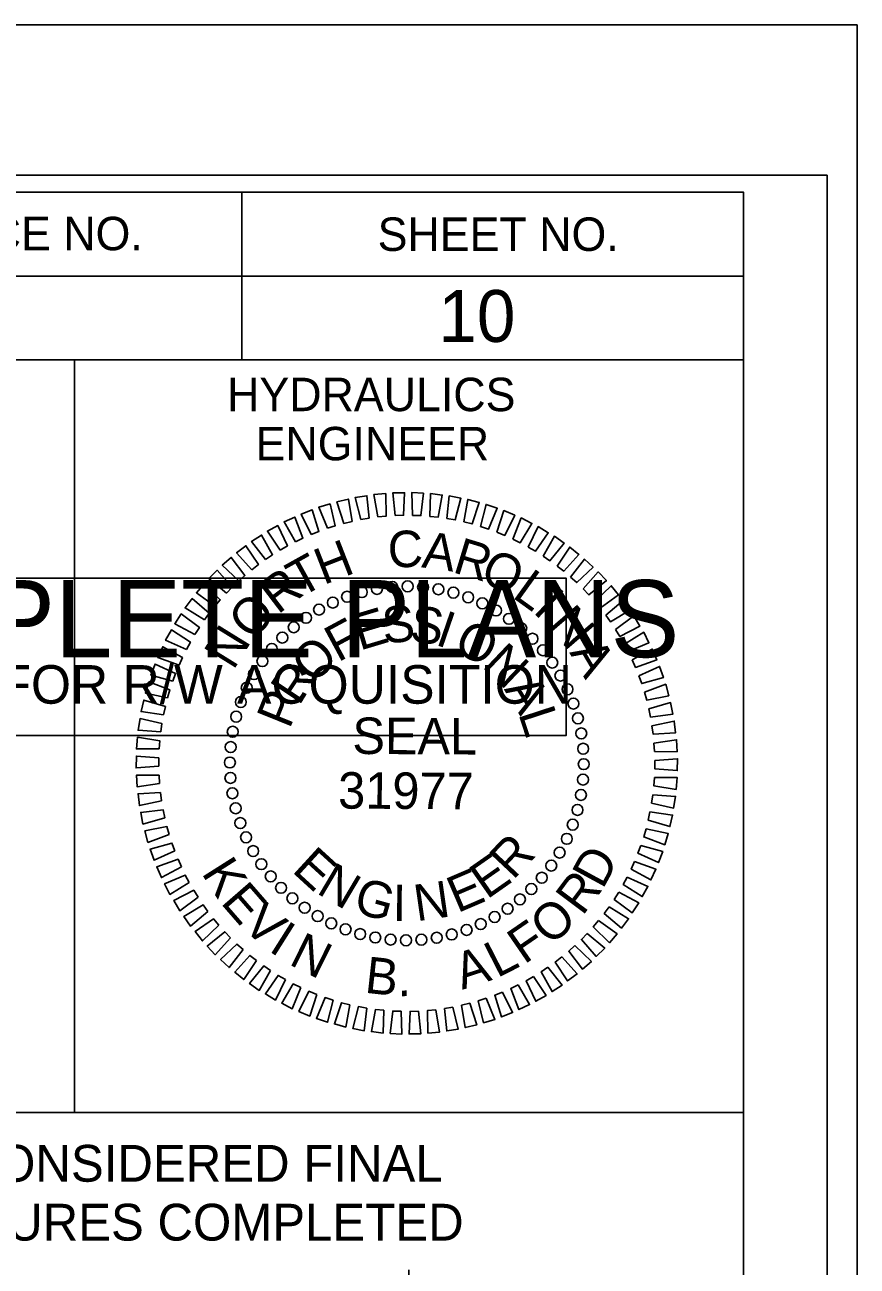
# Model space of a CAD drawing. Extents: x 557032 to 558716, y 513430 to 514605.
# Drawn here: x 558592 to 558716.5, y 514344.9 to 514530.4 of the extents above; entities that cross this region are included whole.
import ezdxf

# ---------------------------------------------------------------- set-up
doc = ezdxf.new("R2010")
doc.units = 0
for name, color, linetype in [('Default', 7, 'Continuous'), ('Sheet Cutting Line CELL', 7, 'Continuous'), ('Sheet Data Field CELL', 7, 'Continuous'), ('Sheet Plot Border Inside CELL', 7, 'Continuous'), ('Sheet Plot Border Outside CELL', 7, 'Continuous'), ('Sheet Profile CELL', 7, 'Continuous'), ('Sheet Profile Grid Major CELL', 7, 'Continuous'), ('Sheet Sticker Exception Certification CELL', 7, 'Continuous'), ('Sheet Sticker Incomplete CELL', 7, 'Continuous')]:
    doc.layers.add(name, color=color, linetype=linetype)

msp = doc.modelspace()

# ---------------------------------------------------------------- linework, layer by layer
at = {"layer": 'Default'}
for points in [[(558639.73, 514455.89), (558638.68, 514459.12), (558640.4, 514459.51), (558640.94, 514456.19)], [(558642.26, 514456.46), (558641.43, 514459.76), (558643.17, 514460.03), (558643.48, 514456.68)], [(558644.81, 514456.85), (558644.22, 514460.2), (558645.98, 514460.34), (558646.05, 514456.98)], [(558647.39, 514457.06), (558647.03, 514460.44), (558648.8, 514460.47), (558648.64, 514457.11)], [(558649.98, 514457.09), (558649.86, 514460.49), (558651.62, 514460.39), (558651.23, 514457.05)], [(558652.56, 514456.94), (558652.68, 514460.34), (558654.43, 514460.12), (558653.8, 514456.81)], [(558655.13, 514456.61), (558655.48, 514460), (558657.21, 514459.65), (558656.36, 514456.4)], [(558657.67, 514456.1), (558658.25, 514459.46), (558659.95, 514458.99), (558658.88, 514455.8)], [(558634.83, 514454.23), (558633.34, 514457.29), (558634.99, 514457.91), (558635.99, 514454.7)], [(558637.25, 514455.15), (558635.97, 514458.3), (558637.66, 514458.81), (558638.44, 514455.53)], [(558660.16, 514455.42), (558660.98, 514458.72), (558662.65, 514458.14), (558661.35, 514455.04)], [(558662.61, 514454.56), (558663.65, 514457.8), (558665.27, 514457.11), (558663.76, 514454.1)], [(558630.21, 514451.91), (558628.3, 514454.73), (558629.85, 514455.57), (558631.29, 514452.53)], [(558632.48, 514453.15), (558630.78, 514456.1), (558632.38, 514456.83), (558633.6, 514453.7)], [(558664.98, 514453.54), (558666.25, 514456.7), (558667.82, 514455.89), (558666.1, 514453)], [(558667.28, 514452.35), (558668.77, 514455.41), (558670.28, 514454.5), (558668.36, 514451.73)], [(558628.03, 514450.51), (558625.93, 514453.19), (558627.42, 514454.14), (558629.07, 514451.21)], [(558669.49, 514451.01), (558671.19, 514453.96), (558672.63, 514452.94), (558670.53, 514450.31)], [(558625.96, 514448.97), (558623.68, 514451.49), (558625.09, 514452.55), (558626.94, 514449.73)], [(558671.6, 514449.51), (558673.5, 514452.34), (558674.87, 514451.22), (558672.59, 514448.75)], [(558624, 514447.28), (558621.55, 514449.64), (558622.88, 514450.79), (558624.92, 514448.11)], [(558673.61, 514447.87), (558675.7, 514450.56), (558676.98, 514449.35), (558674.53, 514447.04)], [(558622.16, 514445.46), (558619.55, 514447.64), (558620.8, 514448.88), (558623.02, 514446.36)], [(558675.49, 514446.1), (558677.76, 514448.63), (558678.96, 514447.34), (558676.36, 514445.2)], [(558620.45, 514443.52), (558617.69, 514445.51), (558618.86, 514446.84), (558621.25, 514444.47)], [(558677.24, 514444.2), (558679.69, 514446.56), (558680.79, 514445.19), (558678.04, 514443.24)], [(558618.88, 514441.46), (558615.99, 514443.26), (558617.06, 514444.66), (558619.61, 514442.47)], [(558678.86, 514442.18), (558681.46, 514444.37), (558682.47, 514442.92), (558679.59, 514441.17)], [(558617.46, 514439.3), (558614.45, 514440.89), (558615.42, 514442.36), (558618.12, 514440.35)], [(558680.33, 514440.05), (558683.08, 514442.05), (558683.98, 514440.54), (558680.99, 514438.99)], [(558616.19, 514437.04), (558613.08, 514438.42), (558613.94, 514439.96), (558616.78, 514438.14)], [(558681.65, 514437.82), (558684.54, 514439.63), (558685.33, 514438.06), (558682.24, 514436.72)], [(558615.09, 514434.7), (558611.89, 514435.86), (558612.64, 514437.45), (558615.59, 514435.84)], [(558682.82, 514435.51), (558685.82, 514437.11), (558686.5, 514435.49), (558683.32, 514434.37)], [(558614.15, 514432.29), (558610.87, 514433.22), (558611.51, 514434.87), (558614.57, 514433.46)], [(558683.81, 514433.12), (558686.92, 514434.51), (558687.49, 514432.84), (558684.24, 514431.95)], [(558613.38, 514429.82), (558610.05, 514430.52), (558610.57, 514432.2), (558613.72, 514431.02)], [(558684.64, 514430.67), (558687.84, 514431.84), (558688.29, 514430.14), (558684.99, 514429.48)], [(558612.78, 514427.3), (558609.41, 514427.77), (558609.81, 514429.49), (558613.04, 514428.52)], [(558685.3, 514428.17), (558688.57, 514429.11), (558688.9, 514427.38), (558685.56, 514426.95)], [(558612.36, 514424.75), (558608.97, 514424.98), (558609.25, 514426.72), (558612.53, 514425.98)], [(558685.78, 514425.63), (558689.11, 514426.34), (558689.31, 514424.59), (558685.95, 514424.39)], [(558612.12, 514422.17), (558608.72, 514422.17), (558608.88, 514423.92), (558612.21, 514423.41)], [(558686.08, 514423.06), (558689.45, 514423.54), (558689.53, 514421.77), (558686.17, 514421.81)], [(558612.06, 514419.58), (558608.67, 514419.34), (558608.71, 514421.1), (558612.06, 514420.83)], [(558686.2, 514420.47), (558689.6, 514420.71), (558689.56, 514418.95), (558686.2, 514419.23)], [(558612.18, 514417), (558608.81, 514416.52), (558608.73, 514418.28), (558612.09, 514418.24)], [(558686.14, 514417.89), (558689.55, 514417.89), (558689.38, 514416.14), (558686.06, 514416.64)], [(558612.48, 514414.43), (558609.16, 514413.72), (558608.95, 514415.47), (558612.31, 514415.66)], [(558685.9, 514415.31), (558689.3, 514415.08), (558689.01, 514413.34), (558685.73, 514414.08)], [(558612.96, 514411.89), (558609.69, 514410.94), (558609.37, 514412.68), (558612.7, 514413.1)], [(558685.48, 514412.76), (558688.85, 514412.29), (558688.45, 514410.57), (558685.23, 514411.54)], [(558613.62, 514409.38), (558610.42, 514408.21), (558609.98, 514409.92), (558613.28, 514410.58)], [(558684.89, 514410.24), (558688.22, 514409.53), (558687.69, 514407.85), (558684.55, 514409.04)], [(558614.45, 514406.93), (558611.34, 514405.54), (558610.78, 514407.21), (558614.02, 514408.1)], [(558684.12, 514407.77), (558687.39, 514406.83), (558686.75, 514405.19), (558683.69, 514406.6)], [(558615.45, 514404.54), (558612.44, 514402.94), (558611.76, 514404.57), (558614.94, 514405.68)], [(558683.18, 514405.36), (558686.38, 514404.2), (558685.62, 514402.6), (558682.67, 514404.22)], [(558616.61, 514402.23), (558613.73, 514400.43), (558612.93, 514402), (558616.02, 514403.33)], [(558682.07, 514403.02), (558685.18, 514401.64), (558684.32, 514400.1), (558681.49, 514401.92)], [(558617.93, 514400.01), (558615.18, 514398), (558614.28, 514399.52), (558617.27, 514401.06)], [(558680.8, 514400.76), (558683.81, 514399.17), (558682.84, 514397.69), (558680.15, 514399.7)], [(558619.4, 514397.88), (558616.8, 514395.69), (558615.8, 514397.14), (558618.67, 514398.89)], [(558679.38, 514398.6), (558682.27, 514396.8), (558681.2, 514395.4), (558678.65, 514397.59)], [(558621.02, 514395.86), (558618.58, 514393.49), (558617.47, 514394.87), (558620.22, 514396.81)], [(558677.81, 514396.54), (558680.57, 514394.54), (558679.41, 514393.22), (558677.01, 514395.59)], [(558622.77, 514393.96), (558620.5, 514391.43), (558619.31, 514392.72), (558621.91, 514394.85)], [(558676.11, 514394.6), (558678.72, 514392.41), (558677.46, 514391.17), (558675.24, 514393.7)], [(558624.66, 514392.18), (558622.57, 514389.5), (558621.28, 514390.71), (558623.73, 514393.02)], [(558674.27, 514392.78), (558676.72, 514390.42), (558675.38, 514389.27), (558673.34, 514391.94)], [(558626.66, 514390.54), (558624.76, 514387.72), (558623.4, 514388.84), (558625.68, 514391.31)], [(558672.3, 514391.09), (558674.58, 514388.56), (558673.17, 514387.51), (558671.32, 514390.32)], [(558628.77, 514389.05), (558627.07, 514386.1), (558625.63, 514387.12), (558627.74, 514389.74)], [(558670.23, 514389.55), (558672.33, 514386.87), (558670.84, 514385.91), (558669.2, 514388.85)], [(558630.98, 514387.7), (558629.49, 514384.64), (558627.99, 514385.56), (558629.9, 514388.32)], [(558633.28, 514386.52), (558632.01, 514383.36), (558630.44, 514384.17), (558632.16, 514387.06)], [(558665.78, 514386.91), (558667.49, 514383.96), (558665.89, 514383.22), (558664.66, 514386.36)], [(558668.05, 514388.15), (558669.96, 514385.33), (558668.41, 514384.48), (558666.97, 514387.52)], [(558635.66, 514385.49), (558634.61, 514382.25), (558632.99, 514382.95), (558634.5, 514385.96)], [(558638.1, 514384.64), (558637.28, 514381.33), (558635.62, 514381.91), (558636.91, 514385.02)], [(558661.01, 514384.91), (558662.29, 514381.76), (558660.6, 514381.25), (558659.82, 514384.52)], [(558663.43, 514385.82), (558664.93, 514382.77), (558663.28, 514382.14), (558662.28, 514385.36)], [(558640.59, 514383.95), (558640.01, 514380.6), (558638.31, 514381.07), (558639.39, 514384.25)], [(558643.13, 514383.45), (558642.78, 514380.06), (558641.05, 514380.4), (558641.9, 514383.66)], [(558645.7, 514383.12), (558645.58, 514379.71), (558643.84, 514379.94), (558644.46, 514383.24)], [(558648.28, 514382.97), (558648.41, 514379.56), (558646.65, 514379.67), (558647.04, 514383.01)], [(558650.87, 514383), (558651.23, 514379.61), (558649.47, 514379.59), (558649.62, 514382.95)], [(558653.45, 514383.21), (558654.04, 514379.86), (558652.29, 514379.71), (558652.21, 514383.08)], [(558656.01, 514383.6), (558656.83, 514380.3), (558655.09, 514380.03), (558654.78, 514383.38)], [(558658.53, 514384.17), (558659.59, 514380.93), (558657.87, 514380.54), (558657.32, 514383.86)]]:
    msp.add_lwpolyline(points, close=True, dxfattribs=at)
for centre in [(558642.41, 514445.61), (558644.66, 514446.1), (558646.95, 514446.39), (558649.26, 514446.48), (558651.56, 514446.36), (558653.85, 514446.05), (558656.1, 514445.54), (558638.07, 514444.05), (558640.2, 514444.92), (558658.3, 514444.84), (558660.42, 514443.94), (558634.07, 514441.77), (558636.02, 514443), (558662.46, 514442.87), (558664.4, 514441.62), (558632.23, 514440.37), (558666.23, 514440.21), (558630.52, 514438.82), (558667.92, 514438.64), (558628.95, 514437.13), (558669.47, 514436.93), (558627.54, 514435.3), (558670.87, 514435.09), (558626.29, 514433.36), (558672.1, 514433.14), (558625.21, 514431.32), (558673.15, 514431.09), (558624.32, 514429.19), (558674.03, 514428.96), (558623.62, 514427), (558674.71, 514426.75), (558623.11, 514424.75), (558675.2, 514424.5), (558622.8, 514422.46), (558675.49, 514422.21), (558622.68, 514420.15), (558675.58, 514419.9), (558622.77, 514417.85), (558675.47, 514417.6), (558623.06, 514415.56), (558675.16, 514415.31), (558623.55, 514413.31), (558674.65, 514413.06), (558624.24, 514411.1), (558673.94, 514410.86), (558625.11, 514408.97), (558673.05, 514408.74), (558626.16, 514406.91), (558671.97, 514406.69), (558627.39, 514404.96), (558670.72, 514404.75), (558628.79, 514403.12), (558669.31, 514402.93), (558630.34, 514401.42), (558667.74, 514401.24), (558632.03, 514399.85), (558666.04, 514399.69), (558633.86, 514398.44), (558635.8, 514397.19), (558662.25, 514397.06), (558664.2, 514398.29), (558637.84, 514396.11), (558639.97, 514395.22), (558658.06, 514395.13), (558660.19, 514396), (558642.16, 514394.51), (558644.41, 514394), (558646.7, 514393.69), (558649.01, 514393.58), (558651.31, 514393.67), (558653.6, 514393.96), (558655.85, 514394.45)]:
    msp.add_circle(centre, 0.818, dxfattribs=at)
at = {"layer": 'Sheet Cutting Line CELL'}
msp.add_line((558716.45, 514530.4), (557032.45, 514530.4), dxfattribs=at)
at = {"layer": 'Sheet Plot Border Inside CELL'}
msp.add_lwpolyline([(557045.45, 513452.85), (558711.95, 513452.85), (558711.95, 514507.95), (557045.45, 514507.95)], close=True, dxfattribs=at)
at = {"layer": 'Sheet Plot Border Outside CELL'}
msp.add_lwpolyline([(557032.45, 513430.4), (558716.45, 513430.4), (558716.45, 514530.4), (557032.45, 514530.4)], close=True, dxfattribs=at)
at = {"layer": 'Sheet Profile CELL'}
for p, q in [((558624.45, 514505.35), (558624.45, 514480.35)), ((558499.4, 514492.85), (558699.45, 514492.85)), ((558599.45, 514480.35), (558599.45, 514367.9))]:
    msp.add_line(p, q, dxfattribs=at)
for points in [[(558699.45, 514505.4), (557199.45, 514505.4), (557199.45, 513455.4), (558699.45, 513455.4)], [(558499.4, 514505.4), (558699.45, 514505.4), (558699.45, 514480.35), (558499.4, 514480.35)], [(558499.4, 514480.35), (558599.45, 514480.35), (558599.45, 514367.85), (558499.4, 514367.85)], [(558599.45, 514480.35), (558699.45, 514480.35), (558699.45, 514367.85), (558599.45, 514367.85)]]:
    msp.add_lwpolyline(points, close=True, dxfattribs=at)
at = {"layer": 'Sheet Profile Grid Major CELL'}
msp.add_lwpolyline([(558649.45, 514344.35), (558649.45, 514005.4), (558699.45, 514005.4), (558699.45, 514355.4)], dxfattribs=at)
at = {"layer": 'Sheet Sticker Exception Certification CELL'}
for p, q in [((558499.4, 514367.85), (558699.44, 514367.85)), ((558499.4, 514367.85), (558699.44, 514367.85)), ((558699.44, 514367.84), (558699.44, 514344.34)), ((558699.44, 514367.84), (558699.44, 514344.34))]:
    msp.add_line(p, q, dxfattribs=at)
at = {"layer": 'Sheet Sticker Incomplete CELL'}
msp.add_lwpolyline([(558525.97, 514424.19), (558525.97, 514447.69), (558672.97, 514447.69), (558672.97, 514424.19)], close=True, dxfattribs=at)

# ---------------------------------------------------------------- texts
at = {"layer": 'Default'}
for s, height, rotation, p in [('H', 5.45, 21.3272, (558636.69, 514446.64)), ('C', 5.45, 1.6879, (558646.36, 514449.27)), ('A', 5.45, 352.1829, (558651.23, 514449.33)), ('R', 5.45, 343.1354, (558655.81, 514448.63)), ('T', 5.45, 29.1164, (558633.2, 514444.71)), ('O', 5.45, 334.9268, (558659.82, 514447.39)), ('R', 5.45, 37.325, (558629.84, 514442.18)), ('L', 5.45, 324.2016, (558664.73, 514444.92)), ('I', 5.45, 316.7365, (558667.83, 514442.68)), ('O', 5.45, 48.0502, (558626.06, 514438.2)), ('E', 5.45, 16.7121, (558642.09, 514436.85)), ('S', 5.45, 4.9498, (558645.67, 514437.93)), ('S', 5.45, 352.9909, (558649.45, 514438.26)), ('I', 5.45, 341.0319, (558653.22, 514437.8)), ('N', 5.45, 310.7965, (558670.07, 514440.62)), ('N', 5.45, 58.2606, (558623.2, 514433.82)), ('F', 5.45, 28.39, (558638.83, 514435.07)), ('O', 5.45, 332.2765, (558655.88, 514436.97)), ('O', 5.45, 44.1988, (558635.12, 514431.7)), ('N', 5.45, 316.4677, (558660.24, 514434.49)), ('A', 5.45, 300.5861, (558673.39, 514436.59)), ('R', 5.45, 56.2982, (558632.99, 514428.5)), ('A', 5.45, 301.4177, (558663.61, 514431.11)), ('P', 5.45, 68.0605, (558631.6, 514425.03)), ('L', 5.45, 288.0818, (558665.78, 514427.47)), ('SEAL', 5.453, 359.7261, (558640.99, 514421.43)), ('31977', 5.453, 359.7261, (558638.85, 514413.26)), ('R', 5.45, 46.7691, (558665.01, 514402.48)), ('E', 5.45, 317.5767, (558631.81, 514403.91)), ('D', 5.45, 61.4266, (558678.4, 514401.08)), ('K', 5.45, 302.3399, (558618.35, 514403.66)), ('E', 5.45, 35.0068, (558661.1, 514399.62)), ('N', 5.45, 329.339, (558635.46, 514400.71)), ('E', 5.45, 23.2446, (558656.69, 514397.6)), ('R', 5.45, 53.218, (558675.39, 514397.1)), ('E', 5.45, 311.0442, (558621.18, 514399.19)), ('G', 5.45, 344.389, (558640.95, 514397.83)), ('I', 5.45, 359.4391, (558646.99, 514396.46)), ('N', 5.45, 8.1945, (558650.6, 514396.41)), ('V', 5.45, 319.0241, (558624.34, 514395.51)), ('O', 5.45, 42.4928, (558670.67, 514392.61)), ('I', 5.45, 327.7094, (558628.33, 514392.05)), ('F', 5.45, 34.5701, (558666.68, 514389.9)), ('N', 5.45, 333.6493, (558631.33, 514390.05)), ('A', 5.45, 18.0575, (558657.4, 514386.16)), ('L', 5.45, 27.105, (558662.62, 514387.88)), ('B', 5.45, 353.7461, (558642.72, 514385.76)), ('.', 5.45, 2.0882, (558647.76, 514385.19))]:
    msp.add_text(s, height=height, rotation=rotation, dxfattribs=at).set_placement(p)
at = {"layer": 'Sheet Data Field CELL'}
msp.add_text('10 ', height=7.75, dxfattribs=at).set_placement((558653.84, 514483.01))
at = {"layer": 'Sheet Profile CELL'}
for s, height, p in [('PROJECT REFERENCE NO.', 5.0001, (558521.62, 514496.71)), ('SHEET NO.', 5, (558644.77, 514496.61)), ('HYDRAULICS', 5, (558622.27, 514472.66)), ('ENGINEER', 5, (558626.52, 514465.31))]:
    msp.add_text(s, height=height, dxfattribs=at).set_placement(p)
at = {"layer": 'Sheet Sticker Exception Certification CELL'}
for s, p in [('DOCUMENT NOT CONSIDERED FINAL', (558520.47, 514357.5)), ('DOCUMENT NOT CONSIDERED FINAL', (558520.47, 514357.5)), ('UNLESS ALL SIGNATURES COMPLETED', (558515.4, 514348.7)), ('UNLESS ALL SIGNATURES COMPLETED', (558515.4, 514348.7))]:
    msp.add_text(s, height=5.5, dxfattribs=at).set_placement(p)
at = {"layer": 'Sheet Sticker Incomplete CELL'}
for s, height, p in [('INCOMPLETE PLANS', 11.52, (558534.92, 514435.89)), ('DO NOT USE FOR R/W ACQUISITION', 5.76, (558538.17, 514428.94))]:
    msp.add_text(s, height=height, dxfattribs=at).set_placement(p)

doc.saveas('drawing.dxf')
